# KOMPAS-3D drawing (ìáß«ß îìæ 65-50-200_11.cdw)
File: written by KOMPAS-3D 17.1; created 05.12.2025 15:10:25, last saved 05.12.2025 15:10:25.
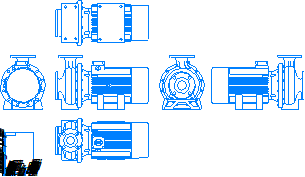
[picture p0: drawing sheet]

Sheet 1: A4, portrait

Title block, sheet 1: name: Насос МНС / 65-50-200_11; material: Сталь 10  ГОСТ 1050-88; mass: 183,14; sheets: 1; sheet format: A4

Views: Вид 1, Спереди, Проекционный вид 2, Проекционный вид 3, Проекционный вид 4, Проекционный вид 6
Referenced files in \\adlc.lan\data\АДЛ_ПКД\3D-модели\ADL production\Насосы ГРАНПАМП\Насосы ГРАНПАМП серии МНС\KOMPAS 3D\: Насос МНС 65-50-200_11.m3d
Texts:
  Andrey
  АДЛ
Dimensions and other numbers on the sheet: 1:1; 1; 65-50-200_11; 183,14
